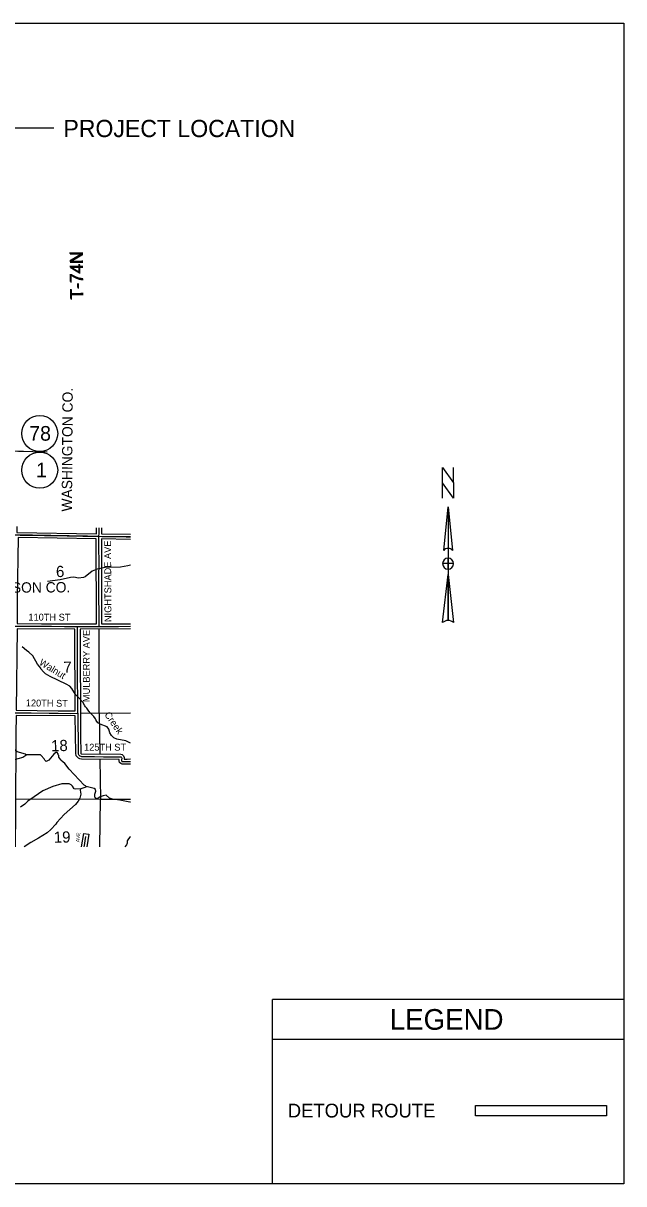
# Model space of a CAD drawing. Extents: x 10133 to 81668, y 7924 to 11018.
# Drawn here: x 12222 to 13268, y 7924 to 9944 of the extents above; entities that cross this region are included whole.
import ezdxf

# ---------------------------------------------------------------- set-up
doc = ezdxf.new("R2010")
doc.units = 0
for name, color, linetype in [('Cell', 7, 'Continuous'), ('SheetBorder', 7, 'Continuous'), ('tdCoCityStreetMajor', 7, 'Continuous'), ('tdCoCityStreetMinor', 7, 'Continuous'), ('tdCoCorpTxt', 7, 'Continuous'), ('tdCoHydroRiver', 7, 'Continuous'), ('tdCoPriNonDiv', 7, 'Continuous'), ('tdCoRROwnerTxt', 7, 'Continuous'), ('tdCoSecRdTxt', 7, 'Continuous'), ('tdCoSectLinePart', 7, 'Continuous'), ('tdCoShieldCoRteHrd', 7, 'Continuous'), ('tdCoShieldStRte', 7, 'Continuous'), ('tdCoStrucNonDivPri', 7, 'Continuous'), ('tdCoStrucSec', 7, 'Continuous'), ('tdCoSurfAsphalt', 7, 'Continuous'), ('tdCoSurfConc', 7, 'Continuous'), ('tdCoTwpBndry', 7, 'Continuous'), ('tdCoTwpNameTxt', 7, 'Continuous')]:
    doc.layers.add(name, color=color, linetype=linetype)

msp = doc.modelspace()

# ---------------------------------------------------------------- linework, layer by layer
at = {"layer": 'Cell'}
for p, q in [((12961.8, 9102.3), (12969.4, 9026.2)), ((12961.8, 9102.3), (12961.8, 8904.5)), ((12954.2, 9026.2), (12954.2, 9026.2)), ((12954.5, 9026.9), (12955.9, 9028.5)), ((12961.8, 8993.9), (12961.8, 8993.9)), ((12952.3, 8900.7), (12961.8, 8984.4))]:
    msp.add_line(p, q, dxfattribs=at)
msp.add_lwpolyline([(12971.3, 9117.5), (12952.3, 9144.1), (12952.3, 9170.7), (12971.3, 9144.1)], close=True, dxfattribs=at)
for points in [[(12952.3, 9117.5), (12952.3, 9170.7), (12971.3, 9144.1), (12971.3, 9170.7)], [(12954.2, 9026.2), (12961.8, 9102.3), (12961.8, 9030)], [(12971.3, 9003.4), (12961.8, 9003.4), (12961.8, 9012.9)], [(12961.8, 8993.9), (12961.8, 9003.4), (12952.3, 9003.4)], [(12961.8, 8904.5), (12961.8, 8984.4), (12971.3, 8900.7)]]:
    msp.add_lwpolyline(points, dxfattribs=at)
for centre, radius, start, end in [((12961.8, 9020.5), 9.51, 90.0204, 143.1257), ((12961.8, 9020.5), 9.5, 36.8481, 90.0218), ((12961.8, 9003.4), 9.51, 90, 180), ((12961.8, 9003.4), 9.51, 0, 90), ((12961.8, 9003.4), 9.51, 180, 270), ((12961.8, 9003.4), 9.51, 270, 360), ((12961.8, 8890.7), 13.8, 89.9894, 133.619), ((12961.8, 8890.7), 13.8, 46.4021, 90.0006)]:
    msp.add_arc(centre, radius, start, end, dxfattribs=at)
at = {"layer": 'SheetBorder'}
msp.add_line((11832.5, 9762.2), (12275.5, 9762.2), dxfattribs=at)
msp.add_lwpolyline([(10132.5, 9944), (13267.5, 9944), (13267.5, 7924), (10132.5, 7924)], close=True, dxfattribs=at)
at = {"layer": 'tdCoCityStreetMajor'}
for points in [[(12354.5, 8894), (12354.4, 8903), (12354.3, 8910.8), (12354.3, 8925.8), (12354.2, 8935.9), (12354.2, 8948.3), (12354.2, 8961.1), (12354, 8973.2), (12354, 8987), (12354.3, 8997.9)], [(12363.8, 8667.3), (12381.8, 8667.3), (12391.4, 8667.2), (12392.6, 8667), (12393.1, 8666.6), (12393.6, 8666), (12393.8, 8665.1), (12393.6, 8661.8), (12393.6, 8660.1), (12393.8, 8659.7), (12394.2, 8659.3), (12395.2, 8658.9), (12396.6, 8658.8), (12403.5, 8658.8), (12408.9, 8658.8)]]:
    msp.add_lwpolyline(points, dxfattribs=at)
at = {"layer": 'tdCoCityStreetMinor'}
for points in [[(12209.3, 9053.2), (12210.4, 9053.3), (12217.2, 9053.2), (12217.6, 9053.2), (12238.3, 9052.7), (12245.8, 9052.8), (12259.5, 9052.6), (12273.7, 9052.2), (12286.2, 9052.1), (12298.9, 9051.9), (12307.8, 9051.7), (12315.9, 9051.6), (12326, 9051.4), (12338, 9051.2), (12351, 9051), (12354.1, 9051)], [(12354.3, 8997.9), (12354.4, 9003.8), (12354.3, 9014.4), (12354, 9023), (12353.9, 9033.3), (12354, 9040), (12354.1, 9049.9), (12354.1, 9051)], [(12354.1, 9051), (12354.3, 9055.7), (12354.4, 9065.5), (12354.4, 9066)], [(12354.1, 9051), (12359.4, 9050.9), (12372.8, 9050.7), (12387.6, 9050.5), (12401.5, 9050.3), (12408.9, 9050.2)], [(12317.3, 8742.9), (12317.5, 8744.5), (12317.5, 8751.3), (12317.3, 8763.5), (12317.2, 8778.2), (12317.1, 8790.7), (12317.1, 8801.4), (12317.1, 8816), (12317, 8828.2), (12317, 8838.2), (12316.8, 8850.7), (12316.9, 8866.4), (12316.7, 8877.5), (12316.8, 8894.1)], [(12205.6, 8743.9), (12208.1, 8743.8), (12236.4, 8743.5), (12267.3, 8743.1), (12283, 8742.9), (12304.5, 8742.8), (12317.3, 8742.9)], [(12317.3, 8742.9), (12317.3, 8742.6), (12317.4, 8739.4), (12317.5, 8731.7), (12317.6, 8717.7), (12317.8, 8702.9), (12318, 8688.8), (12318.1, 8681), (12318.2, 8674.1), (12318.3, 8672.2), (12318.6, 8671.4), (12319.1, 8670.4), (12319.9, 8669.6), (12320.4, 8669.2), (12321.2, 8668.6), (12322.4, 8668.1), (12324, 8667.8), (12329.5, 8667.8), (12346.7, 8667.5), (12362.2, 8667.3), (12363.8, 8667.3)], [(12328.7, 8510.5), (12329.1, 8512.6), (12330.4, 8520.7), (12331.5, 8528.4)]]:
    msp.add_lwpolyline(points, dxfattribs=at)
at = {"layer": 'tdCoHydroRiver'}
for points in [[(12408.9, 9000.9), (12404.5, 8999.5), (12391.7, 8997.3), (12365, 8996.6), (12351.3, 8993.8), (12342.3, 8990.3), (12330.4, 8980.6), (12327.4, 8979.4), (12318.7, 8978.3), (12310.3, 8979.8), (12304.7, 8979.4), (12286.5, 8975.3), (12264.8, 8972.3)], [(12408.9, 8690.7), (12401, 8694.7), (12385.6, 8697.9), (12380.3, 8700), (12376.2, 8704.1), (12373.3, 8709.1), (12371.3, 8715.4), (12368.4, 8719.6), (12356.4, 8723.9), (12352.1, 8726.4), (12349.2, 8730.2), (12349.2, 8731.1), (12348.5, 8731.6), (12348, 8733.5), (12345.3, 8737.2), (12339.3, 8743), (12336.4, 8746.5), (12333, 8751.7), (12330.8, 8754), (12329.8, 8755.9), (12326.1, 8762), (12318.9, 8770.1), (12313.4, 8775.5), (12307.2, 8785.8), (12303.4, 8790.2), (12297.4, 8793.9), (12269.2, 8806.9), (12261.3, 8811.7), (12257.9, 8814.9), (12253.3, 8820.5), (12252.8, 8821.7), (12247, 8828.5), (12239.2, 8843.2), (12232, 8849.5), (12228.4, 8852), (12220.4, 8858.8)], [(12227.2, 8670.6), (12226.2, 8671.6), (12211.9, 8675.6), (12203.5, 8681.6), (12199.2, 8686.2), (12196.7, 8690.4), (12196.2, 8693.5), (12194.8, 8694.9), (12188.6, 8695.5), (12182.7, 8695.2), (12180.6, 8693.5), (12178.3, 8690.1), (12176.6, 8689.6), (12173.8, 8689.8), (12169.5, 8692.1), (12165.4, 8696.5), (12157.2, 8703), (12149.6, 8706.4), (12139.6, 8708.3), (12097.4, 8712.8), (12073.3, 8718.5), (12042.2, 8727.6), (12018.4, 8730.3)], [(12227.2, 8670.6), (12227, 8669.7), (12221.8, 8666.2), (12204.5, 8661.3), (12198.3, 8658.6), (12193.4, 8653.5)], [(12295, 8655.5), (12291.5, 8658.6), (12288.7, 8660.7), (12288, 8661.9), (12285.9, 8664), (12284.6, 8666.4), (12284.3, 8669.5), (12283.5, 8670.7), (12283.5, 8672.4), (12281.6, 8674.5), (12279, 8674.4), (12275.5, 8671.8), (12266.7, 8661.4), (12262.2, 8659), (12259.8, 8661.5), (12258.6, 8663.9), (12253.7, 8669.7), (12252.3, 8670.4), (12227.2, 8670.6)], [(12331.9, 8615.3), (12330.9, 8616.7), (12328.3, 8618.1), (12302.1, 8645.6), (12295, 8655.5)], [(12322.5, 8611.6), (12314, 8611), (12311.1, 8611.6), (12308.2, 8616.1), (12305.6, 8618.6), (12302.2, 8620), (12293.5, 8620.3), (12289.7, 8620.2), (12273.7, 8615.7), (12256.8, 8607.8), (12241.3, 8597.8), (12230.6, 8590), (12225, 8585), (12217.5, 8579.4)], [(12322.5, 8611.6), (12321.6, 8609), (12322.5, 8601.9), (12321.6, 8597.4), (12320.7, 8595), (12318.2, 8590), (12313.3, 8584.2), (12293.5, 8566.8), (12280.7, 8552.6), (12279.4, 8550.2), (12270.5, 8540.6), (12263.8, 8535), (12248.8, 8525.3), (12235.4, 8518.1), (12224, 8510.5)], [(12331.9, 8615.3), (12331.2, 8614.6), (12322.5, 8611.6)], [(12408.9, 8588.4), (12407.9, 8588.5), (12390.4, 8591.5), (12377.6, 8593.2), (12372.3, 8595.2), (12366.8, 8600.3), (12361.6, 8599.5), (12356.4, 8597.3), (12352.2, 8594.4), (12350.1, 8593.9), (12347.4, 8595.5), (12346.9, 8597.1), (12347.1, 8601.9), (12348.9, 8607.1), (12348.4, 8610.2), (12345.9, 8612.3), (12331.9, 8615.3)], [(12408.9, 8528), (12407.4, 8526.7), (12404.2, 8522.9), (12403.3, 8521), (12403.3, 8516.7), (12402.4, 8513.8), (12399, 8510.5)]]:
    msp.add_lwpolyline(points, dxfattribs=at)
at = {"layer": 'tdCoPriNonDiv'}
for p, q in [((12358.9, 8898.5), (12408.9, 8898.9)), ((12403.5, 8663.3), (12408.9, 8663.4))]:
    msp.add_line(p, q, dxfattribs=at)
for points in [[(12211.3, 9068.2), (12211.2, 9057.8), (12349.7, 9055.5), (12349.8, 9066)], [(12358.8, 9065.9), (12358.7, 9055.4), (12408.9, 9054.6)], [(12349.9, 8898.5), (12349.5, 9046.5), (12213.7, 9048.7), (12212.1, 8942.3), (12212.1, 8899.2), (12254, 8898.9), (12349.9, 8898.5)], [(12408.9, 9045.6), (12358.5, 9046.4), (12358.4, 9033.3), (12358.9, 9003.9), (12358.5, 8973.3), (12358.9, 8898.5)], [(12313, 8747.4), (12312.3, 8889.6), (12211.6, 8890.2), (12210.2, 8748.3), (12283, 8747.4), (12313, 8747.4)], [(12408.9, 8889.9), (12321.3, 8889.5), (12322.3, 8702.9), (12322.7, 8674.3), (12322.8, 8673.1), (12323.4, 8672.5), (12392, 8671.7), (12394.7, 8671), (12397.2, 8668.7), (12398.3, 8665.9), (12398.2, 8663.3), (12403.5, 8663.3)], [(12408.9, 8654.6), (12394.5, 8654.5), (12392, 8655.4), (12390, 8657.2), (12389.2, 8659.4), (12389.2, 8662.7), (12323.9, 8663.3), (12321.1, 8663.8), (12318.4, 8665), (12314.7, 8669.1), (12313.7, 8673.7), (12312.9, 8738.4), (12210.1, 8739.3), (12209.7, 8706.9), (12209.2, 8571.5), (12208.5, 8510.5)], [(12324.1, 8510.5), (12327.6, 8533.5), (12336.5, 8532.3), (12333.2, 8510.5)]]:
    msp.add_lwpolyline(points, dxfattribs=at)
at = {"layer": 'tdCoSectLinePart'}
msp.add_lwpolyline([(12056.5, 8893.1), (12071.7, 8893.1), (12106.5, 8893.3), (12116.4, 8893.5), (12140.9, 8893.7), (12167.4, 8894.2), (12195.5, 8894.6), (12207.3, 8894.7), (12208.7, 8894.8), (12230.2, 8894.7), (12254, 8894.4), (12271.8, 8894.4), (12294.1, 8894.2), (12316.8, 8894.1), (12322.5, 8894), (12344.5, 8893.9), (12354.5, 8894), (12360.1, 8894), (12388.3, 8894.2), (12408.9, 8894.4)], dxfattribs=at)
at = {"layer": 'tdCoShieldCoRteHrd'}
msp.add_lwpolyline([(12334.1, 9051.3), (12206.7, 9053.3)], dxfattribs=at)
at = {"layer": 'tdCoStrucNonDivPri'}
for p, q in [((12354.6, 8743.4), (12408.9, 8743.7)), ((12355.7, 8510.5), (12356.6, 8593.3)), ((12356.6, 8593.3), (12408.9, 8593.3))]:
    msp.add_line(p, q, dxfattribs=at)
for points in [[(12212.1, 9199.3), (12222.6, 9199.5)], [(12354.6, 8743.4), (12354.5, 8889.5)], [(12321.9, 8743.5), (12354.6, 8743.4)], [(12354.6, 8743.4), (12355.6, 8671.9)], [(12355.7, 8662.9), (12356.6, 8593.3)], [(12209.3, 8593.8), (12356.6, 8593.3)]]:
    msp.add_lwpolyline(points, dxfattribs=at)
at = {"layer": 'tdCoStrucSec'}
msp.add_lwpolyline([(12163.2, 9200.2), (12264.2, 9197.8)], dxfattribs=at)
at = {"layer": 'tdCoSurfAsphalt'}
for p, q in [((12656.1, 7924), (12656.1, 8244.7)), ((13267.5, 8244.7), (12656.1, 8244.7)), ((13267.5, 8244.7), (13267.5, 7924)), ((12656.1, 8175.5), (13267.5, 8175.5)), ((12656.1, 8175.5), (13267.5, 8175.5)), ((13267.5, 7924), (12656.1, 7924))]:
    msp.add_line(p, q, dxfattribs=at)
msp.add_lwpolyline([(13009.4, 8060.1), (13237.5, 8060.1), (13237.5, 8042.1), (13009.4, 8042.1)], close=True, dxfattribs=at)
at = {"layer": 'tdCoSurfConc'}
for centre in [(12251.1, 9230), (12251.1, 9166.2)]:
    msp.add_circle(centre, 31.3, dxfattribs=at)
at = {"layer": 'tdCoTwpNameTxt'}
msp.add_lwpolyline([(10954.9, 9025.1), (10987.9, 9025.8), (11137.5, 9029.4), (11287.5, 9032.7), (11448.7, 9038.7), (11599.6, 9041.9), (11602.3, 9041.9), (11751.7, 9046.3), (11903.6, 9050), (11906.7, 9050), (12055.4, 9052.4), (12058.4, 9052.5), (12206.7, 9053.3), (12354.1, 9051), (12408.9, 9050.4)], dxfattribs=at)

# ---------------------------------------------------------------- texts
at = {"layer": 'SheetBorder'}
msp.add_text('PROJECT LOCATION', height=30, dxfattribs=at).set_placement((12292.4, 9745.8))
at = {"layer": 'tdCoCorpTxt'}
for s, rotation, p in [('Walnut', 328.5774, (12249, 8828.1)), ('Creek', 304.7329, (12363.1, 8740.5))]:
    msp.add_text(s, height=12, rotation=rotation, dxfattribs=at).set_placement(p)
at = {"layer": 'tdCoRROwnerTxt'}
for s, rotation, p in [('6', 1.1477, (12279.6, 8979.9)), ('7', 1.1478, (12292.5, 8813.3)), ('18', 1.1477, (12271.1, 8676.7)), ('19', 1.1478, (12275.8, 8517.5))]:
    msp.add_text(s, height=19.5, rotation=rotation, dxfattribs=at).set_placement(p)
at = {"layer": 'tdCoSecRdTxt'}
for s, rotation, p in [('WASHINGTON CO.', 89.6308, (12307.3, 9094)), ('JEFFERSON CO.', 0.3231, (12111.8, 8952.3))]:
    msp.add_text(s, height=18, rotation=rotation, dxfattribs=at).set_placement(p)
at = {"layer": 'tdCoShieldStRte'}
for s, height, rotation, p in [('NIGHTSHADE AVE', 12, 90.257, (12375.9, 8901.8)), ('110TH ST', 12, 359.7899, (12231.4, 8904.3)), ('MULBERRY AVE', 12, 90, (12338.3, 8762.4)), ('120TH ST', 12, 359.2962, (12226.9, 8755)), ('125TH ST', 12, 0.0305, (12328.3, 8677.9)), ('AVE', 6, 83.1462, (12319.8, 8518.4))]:
    msp.add_text(s, height=height, rotation=rotation, dxfattribs=at).set_placement(p)
at = {"layer": 'tdCoSurfAsphalt'}
for s, height, p in [('LEGEND', 36, (12860.3, 8192.1)), ('DETOUR ROUTE', 24, (12682.8, 8039.4))]:
    msp.add_text(s, height=height, dxfattribs=at).set_placement(p)
at = {"layer": 'tdCoSurfConc'}
for s, p in [('78', (12232.8, 9217.4)), ('1', (12244.6, 9153.6))]:
    msp.add_text(s, height=25.5, dxfattribs=at).set_placement(p)
at = {"layer": 'tdCoTwpBndry'}
for p in [(12326.2, 9464.2), (12327, 9464.2), (12327.2, 9462.6)]:
    msp.add_text('T-74N', height=22.5, rotation=90.5511, dxfattribs=at).set_placement(p)

doc.saveas('drawing.dxf')
